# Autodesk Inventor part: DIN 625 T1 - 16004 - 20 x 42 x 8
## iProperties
Created: 2006-02
Part Number: DIN 625 T1 - 16004 - 20 x 42 x 8
Material: Steel, Mild
Description: Deep Groove Ball Bearing
Document SubType Name: Modeling
Standard: DIN 625 T1
Designer: Andy Moles
Standards Organization: DIN
Language: en-US
Size Designation: 16004 - 20 x 42 x 8
Categories: <MemberInstance><Categories><Category DisplayName="Shaft Parts" InternalName="7f7aeb1f-a693-4053-b835-cee3144e0d98" Mnemonic="SHFT"><Category DisplayName="Beari
Density: 7.86 g/cm^3
Mass: 44.1545 g
Surface Area: 55.9541 cm^2
Volume: 5.61762 cm^3
Author: Andy Moles
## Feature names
1. Body [Revolution]
2. Fillet1
3. Ball [Revolution]
4. Balls [Circular Pattern]
